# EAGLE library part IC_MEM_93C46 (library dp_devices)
Serial EEPROM 1K
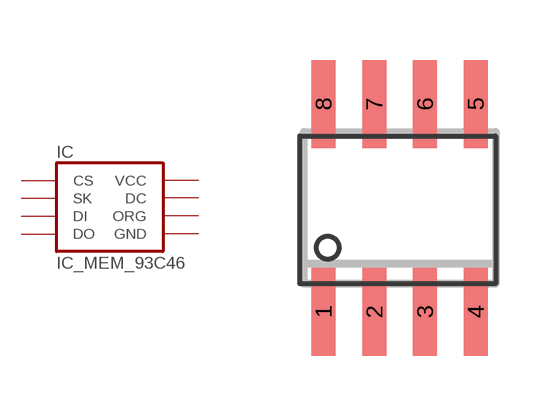
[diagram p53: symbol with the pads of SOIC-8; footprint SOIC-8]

Designator prefix IC

## IC_MEM_93C46 (93C46: 93C46)  [SOIC-8]
1  CS
2  SK
3  DI
4  DO
5  GND
6  ORG
7  DC
8  VCC

## Footprint SOIC-8 (pad centres in mm)
smd 0.6 x 2.2: 1 -1.905,-2.6; 2 -0.635,-2.6; 3 0.635,-2.6; 4 1.905,-2.6; 5 1.905,2.6; 6 0.635,2.6; 7 -0.635,2.6; 8 -1.905,2.6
